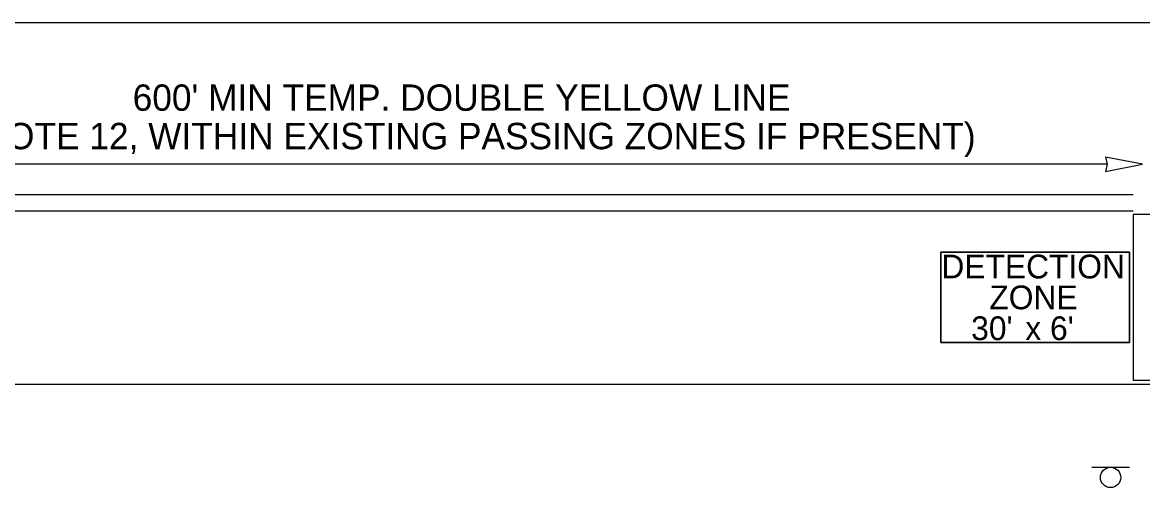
# Model space of a CAD drawing. Extents: x 99976 to 100136, y 99905 to 100011.
# Drawn here: x 100046.886 to 100049.858, y 99946.304 to 99947.539 of the extents above; entities that cross this region are included whole.
import ezdxf

# ---------------------------------------------------------------- set-up
doc = ezdxf.new("R2010")
doc.units = 0
for name, color, linetype in [('RD_MK_LineEdgeWhite', 7, 'Continuous'), ('RD_MK_LineNoPass', 7, 'Continuous'), ('TR_WZ_Sign', 7, 'Continuous'), ('TR_WZ_WorkZoneDetails', 7, 'Continuous'), ('TR_WZ_WorkZoneTextCurrent', 7, 'Continuous')]:
    doc.layers.add(name, color=color, linetype=linetype)

msp = doc.modelspace()

# ---------------------------------------------------------------- linework, layer by layer
at = {"layer": 'RD_MK_LineEdgeWhite'}
for p, q in [((100040.1076, 99947.5393), (100050.4406, 99947.5393)), ((100040.1076, 99946.5793), (100051.1899, 99946.5793))]:
    msp.add_line(p, q, dxfattribs=at)
at = {"layer": 'RD_MK_LineNoPass'}
for p, q in [((100046.4076, 99947.0826), (100049.8326, 99947.0826)), ((100046.4076, 99947.0393), (100049.8326, 99947.0393))]:
    msp.add_line(p, q, dxfattribs=at)
at = {"layer": 'TR_WZ_Sign'}
msp.add_line((100049.7226, 99946.3583), (100049.8226, 99946.3583), dxfattribs=at)
msp.add_circle((100049.7726, 99946.3313), 0.027, dxfattribs=at)
msp.add_circle((100049.7726, 99946.3313), 0.027, dxfattribs=at)
at = {"layer": 'TR_WZ_WorkZoneDetails'}
msp.add_line((100049.7638, 99947.1626), (100046.5013, 99947.1626), dxfattribs=at)
msp.add_lwpolyline([(100049.8576, 99947.1626), (100049.7593, 99947.1819), (100049.7638, 99947.1626), (100049.7593, 99947.1434)], close=True, dxfattribs=at)
for points in [[(100049.8326, 99946.5893), (100049.8826, 99946.5893), (100049.8826, 99947.0293), (100049.8326, 99947.0293), (100049.8326, 99946.5893)], [(100049.8326, 99946.5893), (100049.8826, 99946.5893), (100049.8826, 99947.0293), (100049.8326, 99947.0293), (100049.8326, 99946.5893)], [(100049.3226, 99946.9293), (100049.8226, 99946.9293), (100049.8226, 99946.6893), (100049.3226, 99946.6893), (100049.3226, 99946.9293)], [(100049.3226, 99946.6893), (100049.8226, 99946.6893), (100049.8226, 99946.9293), (100049.3226, 99946.9293), (100049.3226, 99946.6893)]]:
    msp.add_lwpolyline(points, dxfattribs=at)

# ---------------------------------------------------------------- texts
for s, p in [('DETECTION', (100049.3239, 99946.8597)), ('ZONE', (100049.4511, 99946.7778)), ("30'", (100049.4029, 99946.6959)), ("x 6'", (100049.5465, 99946.6959))]:
    msp.add_text(s, height=0.063, dxfattribs=at).set_placement(p)
at = {"layer": 'TR_WZ_WorkZoneTextCurrent'}
for s, p in [("600' MIN TEMP. DOUBLE YELLOW LINE", (100047.1787, 99947.3046)), ('(SEE NOTE 12, WITHIN EXISTING PASSING ZONES IF PRESENT)', (100046.5333, 99947.2026))]:
    msp.add_text(s, height=0.07, dxfattribs=at).set_placement(p)

doc.saveas('drawing.dxf')
